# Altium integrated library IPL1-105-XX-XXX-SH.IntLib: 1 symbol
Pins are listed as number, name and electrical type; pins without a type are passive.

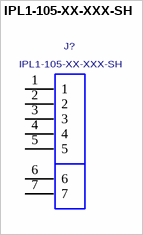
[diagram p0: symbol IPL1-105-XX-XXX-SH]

## IPL1-105-XX-XXX-SH
designator J?
Terminal Assembly, Single Row Horizontal, 5 Pins.; MANUFACTURER: SAMTEC
footprint IPL1-105-XX-XXX-SH
pins: 1, 2, 3, 4, 5, 6, 7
